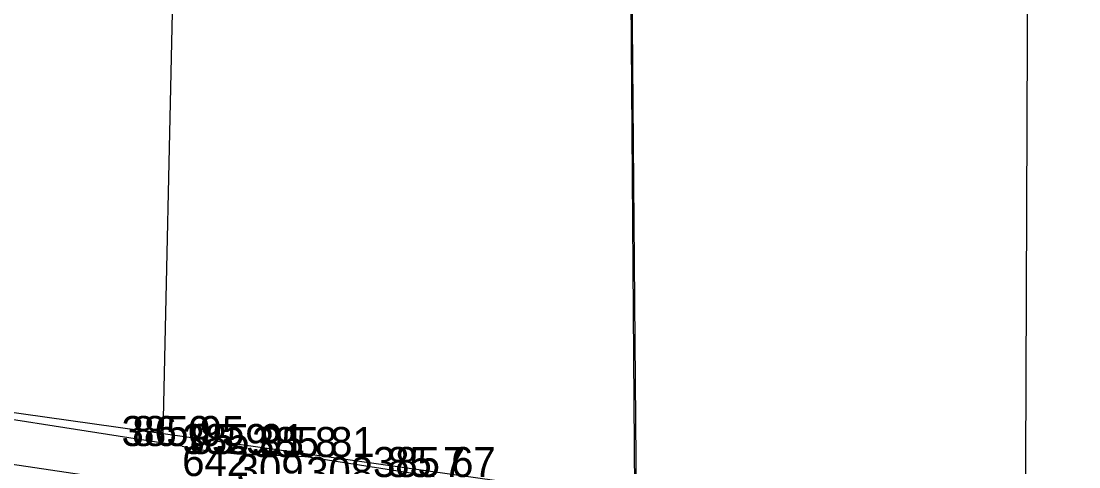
# Model space of a CAD drawing. Extents: x -514509 to -512782, y -1144610 to -1143439.
# Drawn here: x -513107.2 to -513064.89, y -1143573.13 to -1143555.31 of the extents above; entities that cross this region are included whole.
import ezdxf

# ---------------------------------------------------------------- set-up
doc = ezdxf.new("R2010")
doc.units = 0
for name, color, linetype in [('Vrstva 1', 7, 'Continuous'), ('Vrstva 10', 7, 'Continuous'), ('Vrstva 57', 7, 'Continuous'), ('Vrstva 58', 7, 'Continuous'), ('Vrstva 59', 7, 'Continuous'), ('Vrstva 60', 7, 'Continuous'), ('Vrstva 8', 7, 'Continuous')]:
    doc.layers.add(name, color=color, linetype=linetype)

msp = doc.modelspace()

# ---------------------------------------------------------------- linework, layer by layer
at = {"layer": 'Vrstva 1'}
msp.add_lwpolyline([(-513220.491, -1143575.228), (-513193.623, -1143570.982), (-513176.915, -1143569.129), (-513155.694, -1143568.05), (-513138.074, -1143568.989), (-513122.982, -1143570.739), (-513098.68, -1143574.346), (-513082.799, -1143577.731), (-513077.892, -1143579.384), (-513072.257, -1143581.789), (-513063.773, -1143586.163), (-513056.631, -1143588.823), (-513045.948, -1143590.353), (-513035.79, -1143591.42), (-513027.577, -1143592.226), (-513018.616, -1143594.003), (-513003.093, -1143598.799), (-512994.741, -1143602.979), (-512987.23, -1143608.317)], dxfattribs=at)
at = {"layer": 'Vrstva 10'}
for points in [[(-513582.696, -1143761.24), (-513581.966, -1143752.218), (-513543.007, -1143722.265), (-513536.98, -1143726.125), (-513503.11, -1143701.59), (-513467.163, -1143704.368), (-513409.406, -1143670.068), (-513367.763, -1143641.182), (-513337.875, -1143622.14), (-513302.677, -1143606.244), (-513297.569, -1143595.846), (-513289.461, -1143596.696), (-513287.694, -1143584.666), (-513262.147, -1143588.316), (-513251.067, -1143584.844), (-513248.39, -1143579.25), (-513218.784, -1143572.229), (-513191.434, -1143567.629), (-513154.1, -1143564.42), (-513082.649, -1143574.448)], [(-513582.696, -1143761.24), (-513581.966, -1143752.218), (-513543.007, -1143722.265), (-513536.98, -1143726.125), (-513503.11, -1143701.59), (-513467.163, -1143704.368), (-513409.406, -1143670.068), (-513367.763, -1143641.182), (-513337.875, -1143622.14), (-513302.677, -1143606.244), (-513297.569, -1143595.846), (-513289.461, -1143596.696), (-513287.694, -1143584.666), (-513262.147, -1143588.316), (-513251.067, -1143584.844), (-513248.39, -1143579.25), (-513218.784, -1143572.229), (-513191.434, -1143567.629), (-513154.1, -1143564.42), (-513082.649, -1143574.448)], [(-513100.758, -1143572.304), (-513112.55, -1143570.461), (-513123.946, -1143569.095)], [(-513100.758, -1143572.304), (-513100.008, -1143572.461)], [(-513098.577, -1143572.624), (-513099.999, -1143572.464)], [(-513098.577, -1143572.624), (-513099.999, -1143572.464)], [(-513090.677, -1143573.538), (-513095.801, -1143572.735), (-513098.577, -1143572.624)], [(-513090.677, -1143573.538), (-513095.801, -1143572.735), (-513098.577, -1143572.624)]]:
    msp.add_lwpolyline(points, dxfattribs=at)
at = {"layer": 'Vrstva 60'}
for p, q in [((-513100.76, -1143572.3), (-513100.76, -1143572.3)), ((-513098.58, -1143572.62), (-513098.58, -1143572.62)), ((-513095.8, -1143572.74), (-513095.8, -1143572.74))]:
    msp.add_line(p, q, dxfattribs=at)
at = {"layer": 'Vrstva 8'}
for p, q in [((-513082.649, -1143574.448), (-513083.213, -1143500.109)), ((-513100.018, -1143503.277), (-513101.529, -1143571.795))]:
    msp.add_line(p, q, dxfattribs=at)
msp.add_lwpolyline([(-513082.58, -1143574.42), (-513083.213, -1143500.109), (-513066.715, -1143494.873), (-513067.053, -1143579.777)], dxfattribs=at)

# ---------------------------------------------------------------- texts
at = {"layer": 'Vrstva 57'}
for s, p in [('86 0 ', (-513102.757, -1143572.3)), ('85 9 ', (-513100.468, -1143572.62)), ('85 8 ', (-513097.683, -1143572.74)), ('85 7 ', (-513092.563, -1143573.54))]:
    msp.add_text(s, height=1.2, dxfattribs=at).set_placement(p)
at = {"layer": 'Vrstva 58'}
for s, p in [('385 95', (-513103.184, -1143572.3)), ('385 91', (-513100.75, -1143572.62)), ('385 81', (-513097.966, -1143572.74)), ('385 67', (-513093.126, -1143573.54))]:
    msp.add_text(s, height=1.2, dxfattribs=at).set_placement(p)
at = {"layer": 'Vrstva 59'}
for s, p in [('642', (-513100.76, -1143573.5)), ('309', (-513098.58, -1143573.82)), ('308', (-513095.8, -1143573.94))]:
    msp.add_text(s, height=1.2, dxfattribs=at).set_placement(p)

doc.saveas('drawing.dxf')
